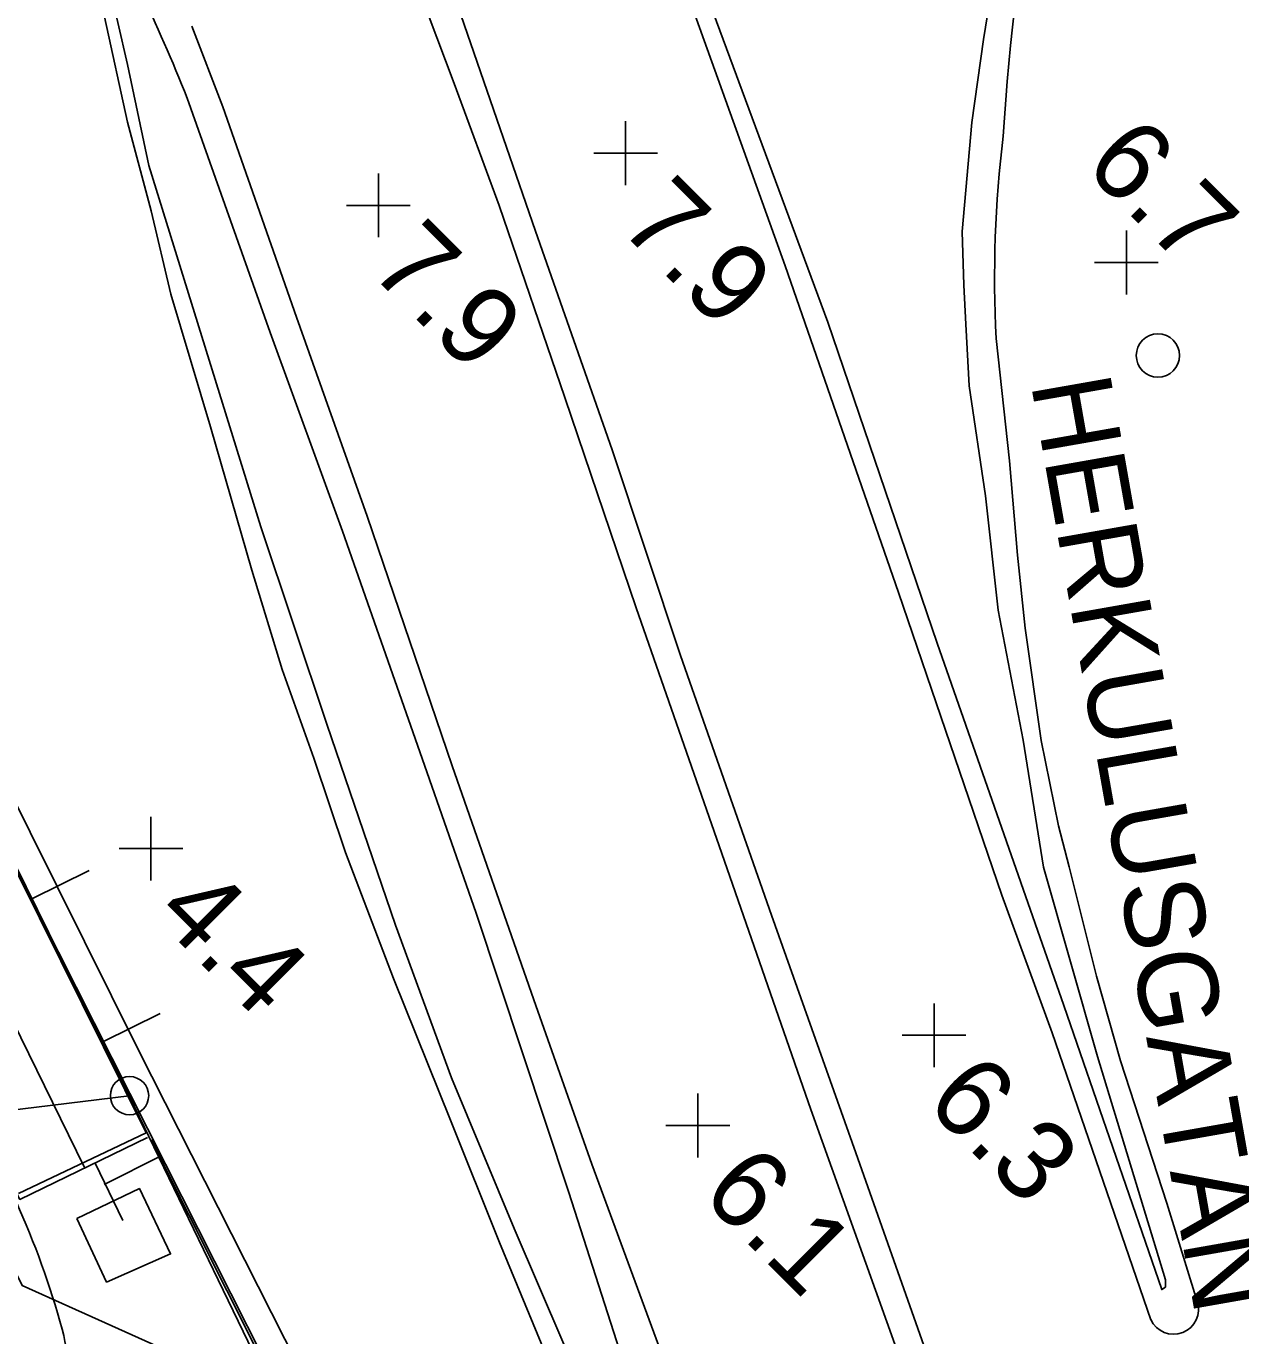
# Model space of a CAD drawing. Extents: x 1596643 to 1597288, y 13057194 to 13057957.
# Drawn here: x 1596926.19 to 1596964.23, y 13057462.53 to 13057503.57 of the extents above; entities that cross this region are included whole.
import ezdxf

# ---------------------------------------------------------------- set-up
doc = ezdxf.new("R2010")
doc.units = 0
for name, color, linetype in [('B kabelränna större än 500 mm NK L', 7, 'Continuous'), ('BAS bro ej def L', 7, 'Continuous'), ('BAS bro kantbalk ej def L', 7, 'Continuous'), ('BAS fastighetsgräns samfällighet L', 7, 'Continuous'), ('BAS gränspunkt P', 7, 'Continuous'), ('BAS gång- cykelväg skymd L', 7, 'Continuous'), ('BAS Level 16', 7, 'Continuous'), ('BAS Level 18', 7, 'Continuous'), ('BAS Level 37', 7, 'Continuous'), ('BAS markytetext T', 7, 'Continuous'), ('BAS stödmur fot L', 7, 'Continuous'), ('BAS stödmur krön L', 7, 'Continuous'), ('BAS trappa riktn pil L', 7, 'Continuous'), ('BAS väg T', 7, 'Continuous'), ('BAS vägbanekant L', 7, 'Continuous'), ('C transformator L', 7, 'Continuous')]:
    doc.layers.add(name, color=color, linetype=linetype)

msp = doc.modelspace()

# ---------------------------------------------------------------- linework, layer by layer
at = {"layer": 'B kabelränna större än 500 mm NK L'}
msp.add_lwpolyline([(1596935.025, 13057457.474), (1596933.135, 13057460.919), (1596926.056, 13057464.105), (1596923.449, 13057469.348)], dxfattribs=at)
at = {"layer": 'BAS bro ej def L'}
for points in [[(1596943.79, 13057460.493), (1596941.475, 13057465.89), (1596939.506, 13057470.621), (1596937.752, 13057475.401), (1596935.601, 13057481.7), (1596933.54, 13057487.886), (1596931.689, 13057493.846), (1596930.024, 13057499.204), (1596929.355, 13057502.374), (1596928.751, 13057505.014), (1596928.377, 13057506.696), (1596928.227, 13057507.736)], [(1596947.495, 13057504.577), (1596951.299, 13057494.302), (1596954.72, 13057484.236), (1596958.693, 13057472.882), (1596961.754, 13057463.979), (1596961.877, 13057464.059), (1596961.87, 13057464.283), (1596959.739, 13057471.283), (1596958.051, 13057477.22), (1596957.413, 13057481.203), (1596956.635, 13057485.278), (1596956.236, 13057488.861), (1596955.723, 13057492.303), (1596955.617, 13057494.236), (1596955.553, 13057495.456), (1596955.504, 13057497.144), (1596955.804, 13057500.555), (1596956.175, 13057503.153), (1596956.575, 13057505.688)], [(1596931.231, 13057501.323), (1596933.825, 13057493.971), (1596936.089, 13057487.752), (1596938.584, 13057480.625), (1596940.277, 13057475.775), (1596943.187, 13057467.026), (1596945.148, 13057460.913)]]:
    msp.add_lwpolyline(points, dxfattribs=at)
msp.add_arc((1596871.916, 13057477.443), 63.942, 21.92953, 28.61082, dxfattribs=at)
at = {"layer": 'BAS bro kantbalk ej def L'}
msp.add_line((1596930.096, 13057468.679), (1596935.426, 13057458.074), dxfattribs=at)
at = {"layer": 'BAS fastighetsgräns samfällighet L'}
msp.add_lwpolyline([(1596872.455, 13057463.088), (1596929.415, 13057470.053)], dxfattribs=at)
at = {"layer": 'BAS gränspunkt P'}
for centre, radius in [((1596929.423, 13057470.058), 0.6), ((1596929.423, 13057470.058), 0.6), ((1596929.416, 13057470.053), 0.001), ((1596929.416, 13057470.053), 0.001)]:
    msp.add_circle(centre, radius, dxfattribs=at)
at = {"layer": 'BAS gång- cykelväg skymd L'}
for centre, radius, start, end in [((1596900.138, 13057455.178), 28.21, 15.541, 24.1924), ((1596916.548, 13057460.18), 11.068, 357.2481, 13.3555)]:
    msp.add_arc(centre, radius, start, end, dxfattribs=at)
at = {"layer": 'BAS Level 16'}
for p, q in [((1596944.963, 13057499.595), (1596944.963, 13057500.595)), ((1596944.963, 13057499.595), (1596944.963, 13057500.595)), ((1596944.963, 13057499.595), (1596943.963, 13057499.595)), ((1596944.963, 13057499.595), (1596943.963, 13057499.595)), ((1596944.963, 13057499.595), (1596945.963, 13057499.595)), ((1596944.963, 13057499.595), (1596944.963, 13057498.595)), ((1596944.963, 13057499.595), (1596945.963, 13057499.595)), ((1596944.963, 13057499.595), (1596944.963, 13057498.595)), ((1596937.217, 13057497.957), (1596937.217, 13057498.957)), ((1596937.217, 13057497.957), (1596937.217, 13057498.957)), ((1596937.217, 13057497.957), (1596936.217, 13057497.957)), ((1596937.217, 13057497.957), (1596936.217, 13057497.957)), ((1596937.217, 13057497.957), (1596938.217, 13057497.957)), ((1596937.217, 13057497.957), (1596937.217, 13057496.957)), ((1596937.217, 13057497.957), (1596938.217, 13057497.957)), ((1596937.217, 13057497.957), (1596937.217, 13057496.957)), ((1596960.646, 13057496.17), (1596960.646, 13057497.17)), ((1596960.646, 13057496.17), (1596960.646, 13057497.17)), ((1596960.646, 13057496.17), (1596959.646, 13057496.17)), ((1596960.646, 13057496.17), (1596959.646, 13057496.17)), ((1596960.646, 13057496.17), (1596961.646, 13057496.17)), ((1596960.646, 13057496.17), (1596960.646, 13057495.17)), ((1596960.646, 13057496.17), (1596961.646, 13057496.17)), ((1596960.646, 13057496.17), (1596960.646, 13057495.17)), ((1596930.094, 13057477.8), (1596930.094, 13057478.8)), ((1596930.094, 13057477.8), (1596930.094, 13057478.8)), ((1596930.094, 13057477.8), (1596929.094, 13057477.8)), ((1596930.094, 13057477.8), (1596929.094, 13057477.8)), ((1596930.094, 13057477.8), (1596931.094, 13057477.8)), ((1596930.094, 13057477.8), (1596930.094, 13057476.8)), ((1596930.094, 13057477.8), (1596931.094, 13057477.8)), ((1596930.094, 13057477.8), (1596930.094, 13057476.8)), ((1596954.623, 13057471.951), (1596954.623, 13057472.951)), ((1596954.623, 13057471.951), (1596954.623, 13057472.951)), ((1596954.623, 13057471.951), (1596953.623, 13057471.951)), ((1596954.623, 13057471.951), (1596953.623, 13057471.951)), ((1596954.623, 13057471.951), (1596955.623, 13057471.951)), ((1596954.623, 13057471.951), (1596954.623, 13057470.951)), ((1596954.623, 13057471.951), (1596955.623, 13057471.951)), ((1596954.623, 13057471.951), (1596954.623, 13057470.951)), ((1596947.221, 13057469.125), (1596947.221, 13057470.125)), ((1596947.221, 13057469.125), (1596947.221, 13057470.125)), ((1596947.221, 13057469.125), (1596946.221, 13057469.125)), ((1596947.221, 13057469.125), (1596946.221, 13057469.125)), ((1596947.221, 13057469.125), (1596948.221, 13057469.125)), ((1596947.221, 13057469.125), (1596947.221, 13057468.125)), ((1596947.221, 13057469.125), (1596948.221, 13057469.125)), ((1596947.221, 13057469.125), (1596947.221, 13057468.125))]:
    msp.add_line(p, q, dxfattribs=at)
at = {"layer": 'BAS Level 18'}
for p, q in [((1596926.365, 13057476.223), (1596928.157, 13057477.112)), ((1596926.365, 13057476.223), (1596928.157, 13057477.112)), ((1596928.588, 13057471.745), (1596930.38, 13057472.634)), ((1596928.588, 13057471.745), (1596930.38, 13057472.634)), ((1596930.418, 13057468.174), (1596928.632, 13057467.274)), ((1596930.418, 13057468.174), (1596928.632, 13057467.274)), ((1596928.342, 13057467.945), (1596929.215, 13057466.145)), ((1596928.342, 13057467.945), (1596929.215, 13057466.145))]:
    msp.add_line(p, q, dxfattribs=at)
at = {"layer": 'BAS Level 37'}
for points in [[(1596929.415, 13057470.053), (1596916.121, 13057497.012)], [(1596929.415, 13057470.053), (1596934.679, 13057459.15)]]:
    msp.add_lwpolyline(points, dxfattribs=at)
at = {"layer": 'BAS stödmur fot L'}
for points in [[(1596910.126, 13057513.576), (1596911.022, 13057509.574), (1596912.93, 13057504.288), (1596915.996, 13057497.063), (1596921.012, 13057486.902), (1596925.938, 13057476.979), (1596929.942, 13057468.896)], [(1596929.942, 13057468.896), (1596925.947, 13057466.993)]]:
    msp.add_lwpolyline(points, dxfattribs=at)
at = {"layer": 'BAS stödmur krön L'}
for points in [[(1596910.214, 13057513.767), (1596911.127, 13057509.619), (1596913.141, 13057503.998), (1596916.093, 13057497.121), (1596921.06, 13057486.966), (1596925.519, 13057477.89), (1596930.551, 13057467.911), (1596935.677, 13057457.761), (1596940.017, 13057449.129), (1596943.748, 13057442.095)], [(1596909.313, 13057500.263), (1596913.287, 13057492.236), (1596917.8, 13057483.163), (1596921.802, 13057475.09), (1596925.989, 13057466.804), (1596929.99, 13057468.744)]]:
    msp.add_lwpolyline(points, dxfattribs=at)
at = {"layer": 'BAS trappa riktn pil L'}
msp.add_line((1596928.012, 13057467.811), (1596911.633, 13057501.175), dxfattribs=at)
at = {"layer": 'BAS vägbanekant L'}
for points in [[(1596909.852, 13057526.126), (1596909.933, 13057524.265), (1596909.962, 13057521.856), (1596910.034, 13057520.017), (1596910.117, 13057518.411), (1596910.4, 13057516.123), (1596910.678, 13057514.709), (1596910.915, 13057513.499), (1596911.213, 13057512.126), (1596911.593, 13057510.742), (1596912.272, 13057508.493), (1596913.245, 13057505.826), (1596914.218, 13057503.383), (1596915.393, 13057500.633), (1596917.977, 13057495.093), (1596921.539, 13057487.973), (1596925.462, 13057480.018), (1596929.708, 13057471.482), (1596935.948, 13057459.15)], [(1596961.412, 13057463.038), (1596958.319, 13057472.029), (1596956.746, 13057476.345), (1596953.504, 13057485.831), (1596949.961, 13057496.061), (1596946.126, 13057506.739), (1596943.357, 13057513.622), (1596941.82, 13057516.942), (1596940.413, 13057519.957), (1596939.397, 13057521.761), (1596938.087, 13057523.993), (1596938.293, 13057523.61)], [(1596927.844, 13057508.45), (1596927.898, 13057507.778), (1596928.004, 13057506.639), (1596928.183, 13057505.683), (1596928.641, 13057503.862), (1596929.356, 13057500.566), (1596930.104, 13057497.788), (1596930.721, 13057495.174), (1596931.96, 13057491.022), (1596933.249, 13057486.525), (1596934.209, 13057483.411), (1596935.201, 13057480.632), (1596936.192, 13057477.68), (1596937.696, 13057473.73), (1596939.473, 13057469.291), (1596941.008, 13057465.453), (1596942.745, 13057461.268), (1596943.762, 13057459.333), (1596943.84, 13057459.15)], [(1596938.443, 13057507.097), (1596939.799, 13057503.927), (1596940.93, 13057500.659), (1596942.141, 13057497.148), (1596944.544, 13057490.297), (1596946.684, 13057483.854), (1596949.527, 13057475.711), (1596952.17, 13057468.27), (1596954.433, 13057461.878), (1596955.457, 13057459.15)], [(1596938.502, 13057504.668), (1596939.595, 13057501.774), (1596940.997, 13057497.956), (1596943.059, 13057491.941), (1596945.29, 13057485.345), (1596947.892, 13057477.884), (1596950.765, 13057469.629), (1596954.512, 13057459.15)], [(1596931.373, 13057503.574), (1596932.345, 13057501.048), (1596934.657, 13057494.452), (1596936.87, 13057488.223), (1596939.531, 13057480.396), (1596942.084, 13057473.057), (1596943.906, 13057467.916), (1596947.131, 13057459.15)], [(1596962.868, 13057463.61), (1596961.918, 13057466.686), (1596960.458, 13057471.154), (1596959.71, 13057473.8), (1596958.854, 13057477.228), (1596958.516, 13057478.51), (1596957.981, 13057481.185), (1596957.472, 13057484.704), (1596957.24, 13057487.001), (1596956.991, 13057489.949), (1596956.567, 13057493.789)]]:
    msp.add_lwpolyline(points, dxfattribs=at)
msp.add_circle((1596961.636, 13057493.253), 0.679, dxfattribs=at)
for centre, radius, start, end in [((1597023.2, 13057496.249), 66.521, 160.93641, 176.6562), ((1596993.141, 13057495.665), 36.622, 172.9986, 182.9363), ((1596962.124, 13057463.365), 0.783, 204.6679, 18.2268)]:
    msp.add_arc(centre, radius, start, end, dxfattribs=at)
at = {"layer": 'C transformator L'}
msp.add_lwpolyline([(1596927.774, 13057466.205), (1596929.735, 13057467.145), (1596930.71, 13057465.098), (1596928.702, 13057464.217), (1596927.774, 13057466.205)], dxfattribs=at)

# ---------------------------------------------------------------- texts
at = {"layer": 'BAS markytetext T'}
for s, p in [('6.7', (1596959.263, 13057499.148)), ('7.9', (1596944.7, 13057497.272)), ('7.9', (1596936.882, 13057495.91)), ('4.4', (1596930.154, 13057475.691)), ('6.3', (1596954.293, 13057469.794)), ('6.1', (1596947.268, 13057466.929))]:
    msp.add_text(s, height=2.5, rotation=315, dxfattribs=at).set_placement(p)
at = {"layer": 'BAS väg T'}
msp.add_text('HERKULUSGATAN', height=2.5, rotation=279.999, dxfattribs=at).set_placement((1596957.65, 13057492.387))

doc.saveas('drawing.dxf')
